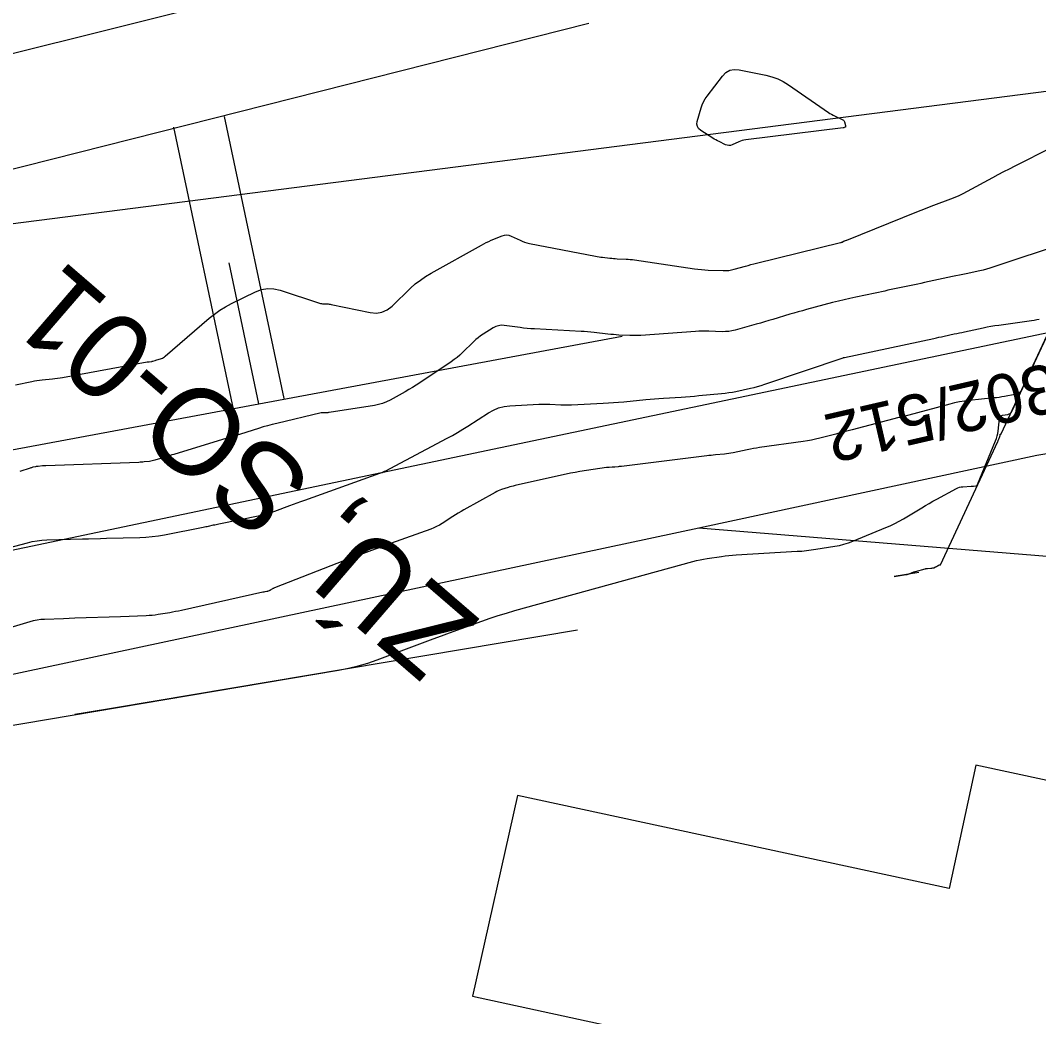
# Model space of a CAD drawing. Extents: x -534481 to -534256, y -1190577 to -1190138.
# Drawn here: x -534408.03 to -534390.37, y -1190542.27 to -1190524.99 of the extents above; entities that cross this region are included whole.
import ezdxf

# ---------------------------------------------------------------- set-up
doc = ezdxf.new("R2010")
doc.units = 0
for name, color, linetype in [('30', 7, 'Continuous'), ('31', 7, 'Continuous'), ('_N_osa', 7, 'Continuous'), ('_N_text', 7, 'Continuous'), ('_tenka', 7, 'Continuous'), ('_velmi_tenka', 7, 'Continuous'), ('Hranice parcel', 7, 'Continuous'), ('Parcelní čísla', 7, 'Continuous'), ('Polygon budovy', 7, 'Continuous')]:
    doc.layers.add(name, color=color, linetype=linetype)

msp = doc.modelspace()

# ---------------------------------------------------------------- linework, layer by layer
at = {"layer": '30'}
for points in [[(-534408.116, -1190531.315), (-534407.831, -1190531.256), (-534407.787, -1190531.248), (-534407.743, -1190531.24), (-534407.698, -1190531.234), (-534407.654, -1190531.229), (-534407.475, -1190531.211), (-534407.431, -1190531.206), (-534407.386, -1190531.2), (-534407.342, -1190531.193), (-534407.298, -1190531.186), (-534405.832, -1190530.919), (-534405.823, -1190530.917), (-534405.814, -1190530.916), (-534405.806, -1190530.915), (-534405.797, -1190530.914), (-534405.756, -1190530.909), (-534405.749, -1190530.908), (-534405.743, -1190530.907), (-534405.737, -1190530.905), (-534405.731, -1190530.904), (-534405.695, -1190530.893), (-534405.683, -1190530.889), (-534405.584, -1190530.857), (-534405.566, -1190530.85), (-534405.549, -1190530.841), (-534405.533, -1190530.831), (-534405.518, -1190530.819), (-534404.755, -1190530.161), (-534404.665, -1190530.088), (-534404.57, -1190530.021), (-534404.472, -1190529.961), (-534404.37, -1190529.907), (-534403.952, -1190529.703), (-534403.847, -1190529.662), (-534403.74, -1190529.644), (-534403.632, -1190529.648), (-534403.522, -1190529.673), (-534402.84, -1190529.899), (-534402.824, -1190529.904), (-534402.808, -1190529.907), (-534402.792, -1190529.91), (-534402.775, -1190529.911), (-534402.708, -1190529.912), (-534402.691, -1190529.913), (-534402.674, -1190529.915), (-534402.658, -1190529.917), (-534402.641, -1190529.92), (-534401.962, -1190530.061), (-534401.856, -1190530.072), (-534401.758, -1190530.057), (-534401.667, -1190530.017), (-534401.583, -1190529.952), (-534401.262, -1190529.641), (-534401.18, -1190529.566), (-534401.093, -1190529.498), (-534401.002, -1190529.435), (-534400.907, -1190529.377), (-534400.034, -1190528.891), (-534399.992, -1190528.868), (-534399.949, -1190528.847), (-534399.906, -1190528.827), (-534399.862, -1190528.808), (-534399.676, -1190528.731), (-534399.636, -1190528.719), (-534399.597, -1190528.715), (-534399.558, -1190528.721), (-534399.519, -1190528.735), (-534399.363, -1190528.808), (-534399.324, -1190528.825), (-534399.284, -1190528.839), (-534399.243, -1190528.851), (-534399.201, -1190528.861), (-534398.056, -1190529.083), (-534398.025, -1190529.089), (-534397.994, -1190529.094), (-534397.962, -1190529.099), (-534397.931, -1190529.102), (-534397.806, -1190529.117), (-534397.774, -1190529.12), (-534397.743, -1190529.123), (-534397.712, -1190529.125), (-534397.68, -1190529.127), (-534397.524, -1190529.134), (-534397.487, -1190529.136), (-534397.451, -1190529.139), (-534397.414, -1190529.143), (-534397.378, -1190529.148), (-534396.337, -1190529.303), (-534396.278, -1190529.311), (-534396.219, -1190529.317), (-534396.16, -1190529.322), (-534396.1, -1190529.325), (-534395.843, -1190529.334), (-534395.793, -1190529.334), (-534395.744, -1190529.33), (-534395.695, -1190529.322), (-534395.647, -1190529.31), (-534395.455, -1190529.256), (-534395.406, -1190529.243), (-534395.358, -1190529.23), (-534395.31, -1190529.217), (-534395.261, -1190529.205), (-534393.805, -1190528.848), (-534393.798, -1190528.846), (-534393.792, -1190528.844), (-534393.786, -1190528.842), (-534393.779, -1190528.839), (-534393.752, -1190528.826), (-534393.743, -1190528.822), (-534393.734, -1190528.818), (-534393.701, -1190528.805), (-534393.697, -1190528.804), (-534392.479, -1190528.313), (-534392.406, -1190528.284), (-534392.333, -1190528.255), (-534392.259, -1190528.227), (-534392.186, -1190528.199), (-534391.891, -1190528.089), (-534391.817, -1190528.06), (-534391.745, -1190528.029), (-534391.675, -1190527.995), (-534391.605, -1190527.959), (-534391.165, -1190527.72), (-534391.069, -1190527.668), (-534390.972, -1190527.617), (-534390.874, -1190527.566), (-534390.777, -1190527.517), (-534390.131, -1190527.193)], [(-534398.369, -1190535.568), (-534406.383, -1190536.918), (-534406.909, -1190537.006), (-534407.085, -1190537.036), (-534406.909, -1190537.006), (-534406.383, -1190536.918), (-534402.51, -1190536.265), (-534402.34, -1190536.232), (-534402.172, -1190536.191), (-534402.006, -1190536.142), (-534401.843, -1190536.085), (-534401.148, -1190535.824), (-534401.008, -1190535.772), (-534400.868, -1190535.72), (-534400.728, -1190535.668), (-534400.587, -1190535.617), (-534400.024, -1190535.414), (-534399.883, -1190535.364), (-534399.741, -1190535.317), (-534399.598, -1190535.273), (-534399.455, -1190535.232), (-534396.365, -1190534.378), (-534396.304, -1190534.362), (-534396.242, -1190534.349), (-534396.18, -1190534.337), (-534396.118, -1190534.327), (-534395.868, -1190534.291), (-534395.806, -1190534.283), (-534395.743, -1190534.276), (-534395.68, -1190534.271), (-534395.617, -1190534.266), (-534394.558, -1190534.203), (-534394.476, -1190534.198), (-534394.394, -1190534.19), (-534394.313, -1190534.179), (-534394.231, -1190534.167), (-534393.906, -1190534.114), (-534393.825, -1190534.099), (-534393.746, -1190534.079), (-534393.667, -1190534.054), (-534393.591, -1190534.025), (-534393.021, -1190533.792), (-534392.942, -1190533.758), (-534392.864, -1190533.721), (-534392.788, -1190533.68), (-534392.713, -1190533.637), (-534392.396, -1190533.446), (-534392.332, -1190533.408), (-534392.267, -1190533.371), (-534392.202, -1190533.334), (-534392.137, -1190533.299), (-534391.793, -1190533.113), (-534391.768, -1190533.101), (-534391.741, -1190533.092), (-534391.714, -1190533.086), (-534391.686, -1190533.083), (-534391.536, -1190533.073), (-534391.516, -1190533.072), (-534391.496, -1190533.07), (-534391.455, -1190533.067), (-534391.446, -1190533.065), (-534391.438, -1190533.061), (-534391.432, -1190533.055), (-534391.427, -1190533.046), (-534391.114, -1190532.285), (-534391.099, -1190532.244), (-534391.087, -1190532.202), (-534391.078, -1190532.159), (-534391.072, -1190532.116), (-534391.049, -1190531.901), (-534391.043, -1190531.879), (-534391.033, -1190531.863), (-534391.017, -1190531.851), (-534390.996, -1190531.844), (-534390.902, -1190531.827), (-534390.88, -1190531.821), (-534390.861, -1190531.81), (-534390.846, -1190531.795), (-534390.834, -1190531.775), (-534389.814, -1190529.586)], [(-534408.239, -1190534.14), (-534407.908, -1190534.054), (-534407.825, -1190534.035), (-534407.742, -1190534.02), (-534407.657, -1190534.011), (-534407.572, -1190534.006), (-534406.955, -1190533.989), (-534406.851, -1190533.986), (-534406.643, -1190533.98), (-534406.539, -1190533.977), (-534405.959, -1190533.961), (-534405.852, -1190533.956), (-534405.744, -1190533.946), (-534405.637, -1190533.932), (-534405.531, -1190533.914), (-534404.857, -1190533.784), (-534404.834, -1190533.78), (-534404.812, -1190533.775), (-534404.79, -1190533.771), (-534404.768, -1190533.766), (-534404.679, -1190533.746), (-534404.657, -1190533.741), (-534404.634, -1190533.736), (-534404.612, -1190533.731), (-534404.59, -1190533.727), (-534403.878, -1190533.582), (-534403.811, -1190533.567), (-534403.745, -1190533.55), (-534403.679, -1190533.529), (-534403.614, -1190533.506), (-534403.357, -1190533.408), (-534403.293, -1190533.384), (-534403.228, -1190533.36), (-534403.163, -1190533.336), (-534403.099, -1190533.313), (-534401.795, -1190532.848), (-534401.779, -1190532.843), (-534401.751, -1190532.834), (-534401.743, -1190532.831), (-534401.736, -1190532.827), (-534401.713, -1190532.814), (-534401.705, -1190532.81), (-534400.628, -1190532.241), (-534400.536, -1190532.192), (-534400.446, -1190532.14), (-534400.357, -1190532.087), (-534400.268, -1190532.031), (-534399.912, -1190531.802), (-534399.826, -1190531.754), (-534399.735, -1190531.717), (-534399.641, -1190531.693), (-534399.542, -1190531.682), (-534399.035, -1190531.653), (-534398.988, -1190531.651), (-534398.94, -1190531.65), (-534398.893, -1190531.65), (-534398.846, -1190531.652), (-534398.658, -1190531.66), (-534398.61, -1190531.662), (-534398.563, -1190531.662), (-534398.516, -1190531.662), (-534398.469, -1190531.66), (-534397.922, -1190531.634), (-534397.832, -1190531.63), (-534397.743, -1190531.624), (-534397.654, -1190531.617), (-534397.565, -1190531.609), (-534397.184, -1190531.572), (-534397.108, -1190531.565), (-534397.031, -1190531.558), (-534396.954, -1190531.552), (-534396.877, -1190531.547), (-534396.569, -1190531.527), (-534396.492, -1190531.521), (-534396.415, -1190531.516), (-534396.338, -1190531.509), (-534396.261, -1190531.502), (-534395.871, -1190531.467), (-534395.807, -1190531.46), (-534395.744, -1190531.451), (-534395.68, -1190531.441), (-534395.618, -1190531.428), (-534395.366, -1190531.374), (-534395.304, -1190531.359), (-534395.242, -1190531.343), (-534395.18, -1190531.325), (-534395.119, -1190531.306), (-534393.759, -1190530.846), (-534393.751, -1190530.843), (-534393.736, -1190530.84), (-534393.734, -1190530.839), (-534392.187, -1190530.509), (-534392.142, -1190530.499), (-534392.098, -1190530.49), (-534392.054, -1190530.48), (-534392.009, -1190530.471), (-534391.832, -1190530.433), (-534391.787, -1190530.424), (-534391.743, -1190530.415), (-534391.699, -1190530.405), (-534391.654, -1190530.396), (-534391.332, -1190530.326), (-534391.264, -1190530.312), (-534391.195, -1190530.299), (-534391.126, -1190530.288), (-534391.057, -1190530.278), (-534390.491, -1190530.199), (-534390.446, -1190530.192), (-534390.402, -1190530.184), (-534390.358, -1190530.174)]]:
    msp.add_lwpolyline(points, dxfattribs=at)
at = {"layer": '31'}
msp.add_lwpolyline([(-534395.715, -1190527.162), (-534395.743, -1190527.165), (-534395.771, -1190527.161), (-534395.799, -1190527.151), (-534395.911, -1190527.096), (-534395.939, -1190527.082), (-534395.967, -1190527.067), (-534395.994, -1190527.052), (-534396.02, -1190527.035), (-534396.23, -1190526.901), (-534396.266, -1190526.87), (-534396.288, -1190526.834), (-534396.296, -1190526.792), (-534396.289, -1190526.745), (-534396.221, -1190526.51), (-534396.202, -1190526.456), (-534396.179, -1190526.404), (-534396.151, -1190526.354), (-534396.118, -1190526.307), (-534395.854, -1190525.96), (-534395.795, -1190525.899), (-534395.726, -1190525.86), (-534395.649, -1190525.844), (-534395.563, -1190525.851), (-534395.1, -1190525.944), (-534394.995, -1190525.971), (-534394.894, -1190526.007), (-534394.798, -1190526.054), (-534394.706, -1190526.111), (-534394.013, -1190526.59), (-534393.988, -1190526.607), (-534393.962, -1190526.622), (-534393.935, -1190526.637), (-534393.908, -1190526.651), (-534393.765, -1190526.719), (-534393.755, -1190526.725), (-534393.747, -1190526.733), (-534393.741, -1190526.742), (-534393.738, -1190526.753), (-534393.721, -1190526.82), (-534393.72, -1190526.828), (-534393.717, -1190526.839), (-534393.717, -1190526.842), (-534393.718, -1190526.844), (-534393.719, -1190526.845), (-534393.722, -1190526.846), (-534393.741, -1190526.854), (-534393.747, -1190526.855), (-534393.757, -1190526.858), (-534393.761, -1190526.859), (-534395.45, -1190527.067), (-534395.481, -1190527.072), (-534395.511, -1190527.079), (-534395.541, -1190527.089), (-534395.57, -1190527.101), (-534395.686, -1190527.153)], close=True, dxfattribs=at)
for points in [[(-534392.445, -1190534.57), (-534392.875, -1190534.642), (-534392.667, -1190534.607), (-534392.658, -1190534.605), (-534392.649, -1190534.603), (-534392.64, -1190534.6), (-534392.631, -1190534.597), (-534392.586, -1190534.581), (-534392.564, -1190534.572), (-534392.534, -1190534.561), (-534392.526, -1190534.559), (-534392.519, -1190534.556), (-534392.511, -1190534.554), (-534392.503, -1190534.552), (-534392.338, -1190534.506), (-534392.331, -1190534.504), (-534392.324, -1190534.503), (-534392.308, -1190534.501), (-534392.298, -1190534.5), (-534392.241, -1190534.497), (-534392.232, -1190534.496), (-534392.223, -1190534.495), (-534392.206, -1190534.492), (-534392.201, -1190534.491), (-534392.197, -1190534.49), (-534392.193, -1190534.489), (-534392.189, -1190534.487), (-534392.158, -1190534.474), (-534392.15, -1190534.471), (-534392.142, -1190534.466), (-534392.121, -1190534.454), (-534392.111, -1190534.448), (-534392.093, -1190534.438), (-534392.088, -1190534.437), (-534392.074, -1190534.436), (-534392.073, -1190534.435), (-534391.077, -1190532.296), (-534391.072, -1190532.287), (-534391.068, -1190532.277), (-534391.064, -1190532.268), (-534391.06, -1190532.259), (-534391.04, -1190532.209), (-534391.039, -1190532.206), (-534391.038, -1190532.202), (-534391.037, -1190532.198), (-534391.036, -1190532.194), (-534391.034, -1190532.176), (-534391.034, -1190532.174), (-534391.033, -1190532.172), (-534391.032, -1190532.171), (-534391.03, -1190532.171), (-534391.021, -1190532.169), (-534391.018, -1190532.168), (-534391.016, -1190532.165), (-534389.189, -1190528.244)], [(-534389.246, -1190528.366), (-534390.653, -1190531.386), (-534390.675, -1190531.423), (-534390.704, -1190531.452), (-534390.74, -1190531.473), (-534390.782, -1190531.485), (-534390.963, -1190531.518), (-534391.008, -1190531.526), (-534391.053, -1190531.533), (-534391.099, -1190531.538), (-534391.145, -1190531.543), (-534391.571, -1190531.586), (-534391.657, -1190531.596), (-534391.742, -1190531.61), (-534391.826, -1190531.627), (-534391.911, -1190531.648), (-534392.708, -1190531.862), (-534392.729, -1190531.867), (-534392.778, -1190531.88), (-534392.792, -1190531.883), (-534393.602, -1190532.094), (-534393.672, -1190532.113), (-534393.743, -1190532.131), (-534393.814, -1190532.15), (-534393.884, -1190532.168), (-534394.166, -1190532.243), (-534394.237, -1190532.26), (-534394.308, -1190532.276), (-534394.38, -1190532.289), (-534394.452, -1190532.3), (-534395.208, -1190532.403), (-534395.262, -1190532.411), (-534395.316, -1190532.42), (-534395.369, -1190532.43), (-534395.423, -1190532.441), (-534395.668, -1190532.493), (-534395.706, -1190532.501), (-534395.743, -1190532.507), (-534395.782, -1190532.513), (-534395.82, -1190532.517), (-534395.973, -1190532.531), (-534396.012, -1190532.534), (-534396.05, -1190532.538), (-534396.088, -1190532.543), (-534396.126, -1190532.547), (-534397.603, -1190532.729), (-534397.617, -1190532.731), (-534397.631, -1190532.732), (-534397.645, -1190532.734), (-534397.659, -1190532.735), (-534397.719, -1190532.741), (-534397.731, -1190532.742), (-534397.743, -1190532.743), (-534397.755, -1190532.744), (-534397.767, -1190532.744), (-534397.816, -1190532.747), (-534397.828, -1190532.747), (-534397.84, -1190532.748), (-534397.852, -1190532.75), (-534397.864, -1190532.751), (-534398.325, -1190532.82), (-534398.406, -1190532.833), (-534398.486, -1190532.848), (-534398.566, -1190532.863), (-534398.646, -1190532.881), (-534399.45, -1190533.064), (-534399.48, -1190533.071), (-534399.509, -1190533.079), (-534399.539, -1190533.087), (-534399.568, -1190533.096), (-534399.685, -1190533.132), (-534399.714, -1190533.142), (-534399.742, -1190533.154), (-534399.769, -1190533.166), (-534399.796, -1190533.18), (-534400.338, -1190533.483), (-534400.387, -1190533.51), (-534400.434, -1190533.539), (-534400.482, -1190533.568), (-534400.528, -1190533.598), (-534400.714, -1190533.719), (-534400.762, -1190533.748), (-534400.81, -1190533.774), (-534400.86, -1190533.797), (-534400.912, -1190533.818), (-534401.609, -1190534.068), (-534401.676, -1190534.092), (-534401.743, -1190534.116), (-534401.81, -1190534.14), (-534401.876, -1190534.164), (-534402.143, -1190534.262), (-534402.21, -1190534.287), (-534402.276, -1190534.312), (-534402.342, -1190534.337), (-534402.409, -1190534.363), (-534403.625, -1190534.838), (-534403.633, -1190534.841), (-534403.642, -1190534.845), (-534403.65, -1190534.85), (-534403.658, -1190534.854), (-534403.695, -1190534.878), (-534403.7, -1190534.881), (-534403.704, -1190534.883), (-534403.709, -1190534.885), (-534403.714, -1190534.887), (-534403.733, -1190534.894), (-534403.738, -1190534.896), (-534403.743, -1190534.897), (-534403.748, -1190534.899), (-534403.753, -1190534.9), (-534403.792, -1190534.907), (-534403.808, -1190534.91), (-534403.824, -1190534.913), (-534405.238, -1190535.228), (-534405.288, -1190535.238), (-534405.338, -1190535.249), (-534405.389, -1190535.258), (-534405.439, -1190535.267), (-534405.642, -1190535.3), (-534405.693, -1190535.308), (-534405.743, -1190535.314), (-534405.795, -1190535.318), (-534405.846, -1190535.321), (-534406.294, -1190535.337), (-534407.087, -1190535.365), (-534407.284, -1190535.372), (-534407.612, -1190535.384), (-534407.677, -1190535.388), (-534407.742, -1190535.396), (-534407.806, -1190535.409), (-534407.869, -1190535.426), (-534408.432, -1190535.594)], [(-534389.891, -1190528.852), (-534391.16, -1190529.276), (-534391.217, -1190529.294), (-534391.275, -1190529.31), (-534391.333, -1190529.325), (-534391.391, -1190529.339), (-534391.626, -1190529.389), (-534391.684, -1190529.402), (-534391.743, -1190529.415), (-534391.802, -1190529.427), (-534391.86, -1190529.439), (-534392.351, -1190529.543), (-534392.409, -1190529.555), (-534392.466, -1190529.567), (-534392.523, -1190529.579), (-534392.58, -1190529.591), (-534392.81, -1190529.639), (-534392.867, -1190529.651), (-534392.924, -1190529.663), (-534392.982, -1190529.675), (-534393.039, -1190529.688), (-534393.542, -1190529.794), (-534393.642, -1190529.816), (-534393.742, -1190529.839), (-534393.842, -1190529.864), (-534393.942, -1190529.89), (-534394.392, -1190530.009), (-534394.466, -1190530.029), (-534394.539, -1190530.05), (-534394.612, -1190530.071), (-534394.685, -1190530.092), (-534394.976, -1190530.18), (-534395.049, -1190530.201), (-534395.122, -1190530.223), (-534395.195, -1190530.244), (-534395.269, -1190530.265), (-534395.632, -1190530.366), (-534395.688, -1190530.38), (-534395.744, -1190530.389), (-534395.801, -1190530.393), (-534395.859, -1190530.394), (-534396.09, -1190530.386), (-534396.148, -1190530.384), (-534396.206, -1190530.385), (-534396.264, -1190530.386), (-534396.322, -1190530.39), (-534397.267, -1190530.457), (-534397.315, -1190530.46), (-534397.362, -1190530.461), (-534397.41, -1190530.461), (-534397.457, -1190530.459), (-534397.648, -1190530.451), (-534397.695, -1190530.449), (-534397.743, -1190530.445), (-534397.79, -1190530.441), (-534397.838, -1190530.436), (-534398.08, -1190530.408), (-534398.136, -1190530.402), (-534398.193, -1190530.397), (-534398.249, -1190530.392), (-534398.306, -1190530.389), (-534399.111, -1190530.346), (-534399.174, -1190530.342), (-534399.238, -1190530.337), (-534399.301, -1190530.33), (-534399.364, -1190530.323), (-534399.64, -1190530.286), (-534399.691, -1190530.283), (-534399.739, -1190530.289), (-534399.786, -1190530.304), (-534399.831, -1190530.328), (-534400.006, -1190530.439), (-534400.049, -1190530.468), (-534400.09, -1190530.498), (-534400.13, -1190530.531), (-534400.168, -1190530.567), (-534400.363, -1190530.757), (-534400.409, -1190530.8), (-534400.456, -1190530.84), (-534400.506, -1190530.878), (-534400.557, -1190530.914), (-534401.103, -1190531.279), (-534401.165, -1190531.32), (-534401.227, -1190531.359), (-534401.291, -1190531.397), (-534401.355, -1190531.434), (-534401.614, -1190531.579), (-534401.68, -1190531.612), (-534401.747, -1190531.639), (-534401.817, -1190531.659), (-534401.889, -1190531.674), (-534402.675, -1190531.796), (-534402.687, -1190531.797), (-534402.698, -1190531.798), (-534402.709, -1190531.799), (-534402.721, -1190531.799), (-534402.767, -1190531.798), (-534402.778, -1190531.799), (-534402.789, -1190531.799), (-534402.801, -1190531.801), (-534402.812, -1190531.803), (-534403.583, -1190531.983), (-534403.663, -1190532.003), (-534403.742, -1190532.024), (-534403.821, -1190532.046), (-534403.899, -1190532.07), (-534404.212, -1190532.169), (-534404.29, -1190532.194), (-534404.369, -1190532.218), (-534404.447, -1190532.243), (-534404.526, -1190532.266), (-534405.367, -1190532.521), (-534405.405, -1190532.532), (-534405.442, -1190532.544), (-534405.48, -1190532.555), (-534405.517, -1190532.567), (-534405.698, -1190532.623), (-534405.721, -1190532.63), (-534405.744, -1190532.635), (-534405.766, -1190532.639), (-534405.79, -1190532.643), (-534405.882, -1190532.653), (-534405.906, -1190532.656), (-534405.929, -1190532.658), (-534405.952, -1190532.659), (-534405.976, -1190532.66), (-534407.586, -1190532.718), (-534407.602, -1190532.718), (-534407.617, -1190532.719), (-534407.633, -1190532.721), (-534407.649, -1190532.722), (-534407.719, -1190532.729), (-534407.731, -1190532.73), (-534407.743, -1190532.732), (-534407.755, -1190532.734), (-534407.766, -1190532.736), (-534407.813, -1190532.746), (-534407.825, -1190532.749), (-534407.836, -1190532.752), (-534407.848, -1190532.755), (-534407.859, -1190532.759), (-534408.038, -1190532.821)], [(-534411.243, -1190537.736), (-534404.293, -1190536.566)]]:
    msp.add_lwpolyline(points, dxfattribs=at)
at = {"layer": '_N_osa'}
msp.add_line((-534422.24, -1190529.075), (-534398.624, -1190523.185), dxfattribs=at)
at = {"layer": '_N_text'}
msp.add_line((-534380.58, -1190524.995), (-534411.965, -1190529.007), dxfattribs=at)
at = {"layer": '_tenka'}
for p, q in [((-534421.77, -1190531.02), (-534398.17, -1190525.04)), ((-534427.69, -1190536.07), (-534397.59, -1190530.47))]:
    msp.add_line(p, q, dxfattribs=at)
at = {"layer": '_velmi_tenka'}
for p, q in [((-534403.454, -1190531.55), (-534404.487, -1190526.659)), ((-534404.335, -1190531.736), (-534405.368, -1190526.845)), ((-534403.895, -1190531.643), (-534404.411, -1190529.198))]:
    msp.add_line(p, q, dxfattribs=at)
at = {"layer": 'Hranice parcel'}
for points in [[(-534424.26, -1190537.56), (-534383.41, -1190528.98), (-534381.269, -1190528.899)], [(-534381.658, -1190531.109), (-534390.4, -1190532.54), (-534396.26, -1190533.8)], [(-534396.26, -1190533.8), (-534408.82, -1190536.48), (-534409.82, -1190536.63)], [(-534382.333, -1190534.934), (-534396.26, -1190533.8)]]:
    msp.add_lwpolyline(points, dxfattribs=at)
at = {"layer": 'Polygon budovy'}
msp.add_lwpolyline([(-534400.19, -1190541.92), (-534394.59, -1190543.13), (-534394.89, -1190544.51), (-534390.54, -1190545.47), (-534390.82, -1190546.76), (-534389.15, -1190547.11), (-534390.54, -1190553.66), (-534381.04, -1190555.72), (-534378.2, -1190543), (-534387.05, -1190541.1), (-534386.59, -1190538.96), (-534391.46, -1190537.91), (-534391.92, -1190540.05), (-534399.41, -1190538.44)], close=True, dxfattribs=at)

# ---------------------------------------------------------------- texts
at = {"layer": '_N_text'}
msp.add_text('ZÚ, SO-01', height=1.5, rotation=139.2051, dxfattribs=at).set_placement((-534400.02, -1190535.416))
at = {"layer": 'Parcelní čísla'}
msp.add_text('2302/512', height=0.85, rotation=193, dxfattribs=at).set_placement((-534389.518, -1190530.781))

doc.saveas('drawing.dxf')
